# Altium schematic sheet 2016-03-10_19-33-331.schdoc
size 331 x 142 mm; SheetNumber: 1; SheetTotal: 1
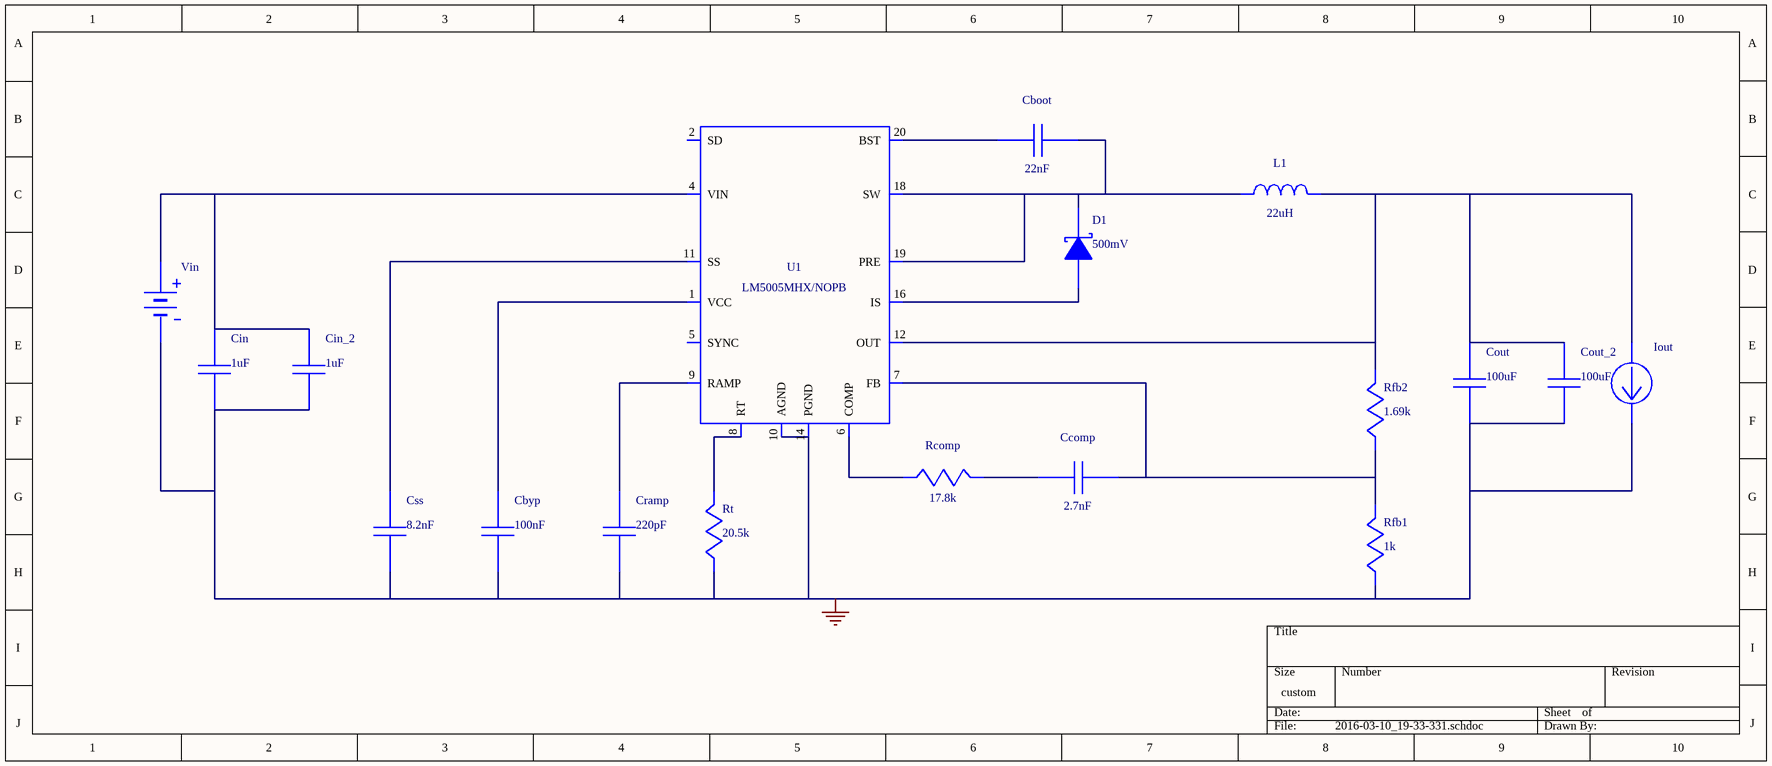
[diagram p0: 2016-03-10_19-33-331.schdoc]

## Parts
Cboot  value 22nF  (hidden comment: C0805C223K5RACTU)
Cbyp  value 100nF  (hidden comment: 08053C104KAT2A)
Ccomp  value 2.7nF  (hidden comment: CC0805KRX7R9BB272)
Cin  value 1uF  (hidden comment: GENERIC_CAPACITOR)
Cin_2  value 1uF  (hidden comment: GENERIC_CAPACITOR)
Cout  value 100uF  (hidden comment: GRM31CR60J107ME39L)
Cout_2  value 100uF  (hidden comment: GRM31CR60J107ME39L)
Cramp  value 220pF  (hidden comment: C0805C221J5GACTU)
Css  value 8.2nF  (hidden comment: GRM155R71E822KA01D)
D1  value 500mV  (hidden comment: B340A-13-F)
Iout  WB_CURRENT_LOAD  (value not drawn)
L1  value 22uH  (hidden comment: SDR1307-220ML)
Rcomp  value 17.8k  (hidden comment: ERJ-6ENF1782V)
Rfb1  value 1k  (hidden comment: ERJ-6ENF1001V)
Rfb2  value 1.69k  (hidden comment: ERJ-6ENF1691V)
Rt  value 20.5k  (hidden comment: ERJ-6ENF2052V)
U1  LM5005MHX/NOPB
Vin  WB_BATTERY  (value not drawn)

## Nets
0: Cbyp.2 Cin.2 Cin_2.2 Cout.2 Cout_2.2 Cramp.2 Css.2 Iout.2(-) Rfb1.2 Rt.2 U1.10(AGND) U1.13(PGND) U1.14(PGND) U1.21(EP) Vin.2(-)
NetCboot_1: Cboot.1 D1.1(K) L1.1 U1.17(SW) U1.18(SW) U1.19(PRE)
NetCboot_2: Cboot.2 U1.20(BST)
NetCbyp_1: Cbyp.1 U1.1(VCC)
NetCcomp_1: Ccomp.1 Rfb1.1 Rfb2.2 U1.7(FB)
NetCcomp_2: Ccomp.2 Rcomp.1
NetCin_1: Cin.1 Cin_2.1 U1.3(VIN) U1.4(VIN) Vin.1(+)
NetCout_1: Cout.1 Cout_2.1 Iout.1(+) L1.2 Rfb2.1 U1.12(OUT)
NetCramp_1: Cramp.1 U1.9(RAMP)
NetCss_1: Css.1 U1.11(SS)
NetD1_2: D1.2(A) U1.15(IS) U1.16(IS)
NetRcomp_2: Rcomp.2 U1.6(COMP)
NetRt_1: Rt.1 U1.8(RT)

Not connected (* = marked no-connect by the designer): U1 2(SD) 5(SYNC)

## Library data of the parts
Cboot = C0805C223K5RACTU: Manufacturer Name: Kemet
Cbyp = 08053C104KAT2A: Manufacturer Name: AVX
Ccomp = CC0805KRX7R9BB272: CC0805KRX7R9BB27; Manufacturer Name: Yageo America
Cin Cin_2 = GENERIC_CAPACITOR: C1608X7R1V105K08; Manufacturer Name: TDK
Cout Cout_2 = GRM31CR60J107ME39L: GRM31CR60J107ME3; Manufacturer Name: MuRata
Cramp = C0805C221J5GACTU: Manufacturer Name: Kemet
Css = GRM155R71E822KA01D: GRM155R71E822KA0; Manufacturer Name: MuRata
D1 = B340A-13-F: Manufacturer Name: Diodes Inc.
Iout = WB_CURRENT_LOAD: Value: UNLISTED
L1 = SDR1307-220ML: Manufacturer Name: Bourns
Rcomp = ERJ-6ENF1782V: Manufacturer Name: Panasonic
Rfb1 = ERJ-6ENF1001V: Manufacturer Name: Panasonic
Rfb2 = ERJ-6ENF1691V: Manufacturer Name: Panasonic
Rt = ERJ-6ENF2052V: Manufacturer Name: Panasonic
U1 = LM5005MHX/NOPB: Manufacturer Name: Texas Instruments; Value: UNLISTED
Vin = WB_BATTERY: Value: UNLISTED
